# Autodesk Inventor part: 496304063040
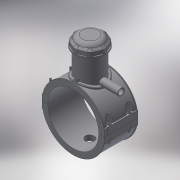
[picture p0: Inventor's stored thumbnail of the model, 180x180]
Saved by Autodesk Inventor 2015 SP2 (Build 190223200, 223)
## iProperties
Created: 2017-07
Part Number: 496304063040
Material: Generic
Description: PLASSON TAPPING SADDLE 63x40
Document SubType Name: Modeling
Designer: KIM
Mass: 450.935 g
Surface Area: 1373.71 cm^2
Volume: 450.935 cm^3
Density: 1 g/cm^3
Appearance: Default
Author: KIM
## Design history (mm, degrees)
derived "496304.ipt"
feature "Solid1::496304.ipt"
feature "Solid2::496304.ipt"
feature "Solid4::496304.ipt"
feature "Solid5::496304.ipt"
tag "TaggingFeature1"
body "Solid1"
body "Solid2"
other parameters: "d0" = 63, "d3" = 15.75, "d4" = 118, "d5" = 0, "d6" = 0.1, "d8" = 0, "d19" = 6, "d20" = 6, "d21" = 70.8, "d23" = 0, "d24" = 35.4, "d26" = 0, "d29" = 3, "d30" = 21, "d31" = 6, "d32" = 0, "d33" = 0, "d34" = 0.6, "d40" = 42.588, "d41" = 63, "d43" = 0, "d45" = 0, "d47" = 111.75, "d70" = 15, "d72" = 0, "d73" = 6, "d75" = 5, "d76" = 0, "d77" = 3.15, "d78" = 61.5, "d79" = 15, "d80" = 47.2, "d82" = 5 deg, "d84" = 4, "d85" = 14, "d86" = 0, "d87" = 3, "d88" = 0, "d89" = 1, "d90" = 1, "d91" = 94.4, "d92" = 0, "d93" = 0.5, "d94" = 33.15789, "d96" = 83.538, "d97" = 2.36, "d98" = 0, "d102" = 0.63, "d120" = 140 deg, "d121" = 24.228, "d122" = 20 deg, "d123" = 163.8, "d124" = 49.14, "d126" = 0, "d143" = 64.89, "d145" = 14.53846, "d149" = 0.945, "d150" = 15.99231, "d153" = 118, "d154" = 0, "d156" = 40.95, "d157" = 160 deg, "d159" = 3.78, "d161" = 0.945, "d162" = 70.8, "d163" = 0, "d164" = 31.5, "d167" = 6.3, "d168" = 39.95122, "d170" = 3.375, "d172" = 0, "d173" = 1, "d175" = 31.5, "d176" = 20 deg, "d177" = 4.41, "d178" = 18.9, "d180" = 0, "d183" = 7.56, "d184" = 3.528, "d185" = 38.35, "d186" = 38.35, "d187" = 40.95, "d188" = 5.67, "d189" = 4.41, "d190" = 0, "d191" = 61.425, "d193" = 6.3, "d194" = 4.13, "d195" = 90 deg, "d197" = 0, "d199" = 0, "d200" = 9.45, "d202" = 0, "d203" = 177, "d204" = 59.85, "d205" = 44.1, "d206" = 53.55, "d207" = 132.75, "d208" = 138.06, "d209" = 164.61, "d210" = 54.18, "d211" = 63, "d212" = 50.4, "d213" = 39.6, "d216" = 0, "d217" = 6.3, "d218" = 6.3, "d219" = 1.26, "d222" = 63, "d224" = 0, "d230" = 3.78, "d233" = 6, "d237" = 35.4, "d238" = 6.02433, "d240" = 35.4, "d241" = 35.4, "d242" = 35.4, "d243" = 6, "d244" = 35.4, "d245" = 35.4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
